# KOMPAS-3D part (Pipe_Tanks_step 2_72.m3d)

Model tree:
1. X Axis
2. Y Axis
3. Z Axis  (labels: T-Bend Dn 50; Pipe Dn 50)
     Òîëùèíà ñòåíêè 1 = 1

Referenced files in C:\Documents and Settings\kashirsky\Мои документы\Camtasia Studio\Pipelines3D\Tanks\: Tanks_step 4.a3d
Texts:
  Pipe Dn 50
  Steel ASTM A295
  Three Point Plane
  Plane at Angle
  Line and Point Plane
  Axis through Two Vertices
  Axis of Feature
  Axis of Conical Surface
  Axis through Edge
  Trim by Surface
  Trim by Sketch
  Feature with No History
  Intersection Axis of Two Planes
  Two Line Plane
  Line and Face Plane
  Bend by line
  Hole in sheet body
  Cut in sheet body
  Point in CM
  Linear Dimension from Line to Point
  Surface Finish Symbol
  Geometric Tolerance Symbol
  Leader #1
  Leader #2
  Leader #3
  Shape Deviations and Datum
  Node point number
  Mark of coordination axis
  Node point designation
  Mark/Reference designation with leader
  Mark/reference designation on line
  Mark/Reference designation without leader
  T-Bend Dn 50
  Plane of section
